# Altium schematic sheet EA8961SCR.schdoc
size 127 x 101 mm
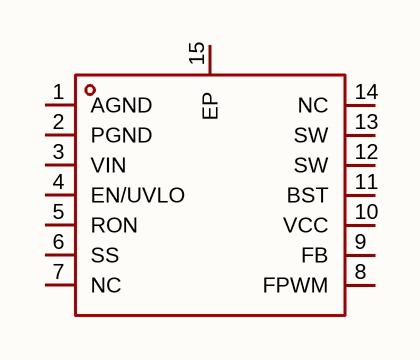
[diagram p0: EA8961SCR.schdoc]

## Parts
U?  ea8961scr  [TSSOP-14_L5.0-W4.4-P0.65-LS6.4-BL-EP3.2]  (value not drawn)

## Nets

Not connected (* = marked no-connect by the designer): U? 1(AGND) 2(PGND) 3(VIN) 4(EN/UVLO) 5(RON) 6(SS) 7(NC) 8(FPWM) 9(FB) 10(VCC) 11(BST) 12(SW) 13(SW) 14(NC) 15(EP)

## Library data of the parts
U? = ea8961scr: 功能类型:降压型;工作电压:5V~100V;输出电压:-;输出电流:1A;输出类型:可调;; Manufacturer: everanalog(申风); AddInBom: yes; ModelId: 9ea67a8c131e42bfb352421a8bac371a; ModelTransform: 196.85,251.968,0,0,0,0,0,0,0; Function: 降压型; Output Current: 1A; Frequency - Switching: 300kHz；1MHz; Synchronous Rectifier: 是; Number of Outputs: 1; Topology: 降压式; Quiescent Current: 1.3mA; Switch tube (built-in/external): 内置; Output Type: 可调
